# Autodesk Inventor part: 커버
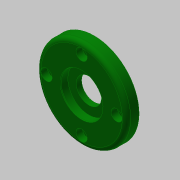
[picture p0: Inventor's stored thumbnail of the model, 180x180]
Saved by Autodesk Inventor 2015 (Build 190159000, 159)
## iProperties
Created: 2019-06
Part Number: 커버
Material: 알루미늄 6061
Document SubType Name: Modeling
Designer: mduedu
Density: 1 g/cm^3
Appearance: 진녹색
Author: mduedu
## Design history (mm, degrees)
sketch "스케치1"
  geometry: L1 (0, 0)-(9, 0); L2 (9, 0)-(9, 32); L3 (9, 32)-(0, 32); L4 (0, 32)-(0, 0); L5 (9, 0)-(12, 0); L6 (12, 0)-(12, 20); L7 (12, 20)-(9, 20); L8 (9, 20)-(9, 0)
  constraints: 16 end point, 4 parallel, 2 horizontal, 2 perpendicular
  dimensions: "d0" = 64 diameter of L3 L1; "d2" = 40 diameter of L7 L5; "d3" = 12 distance between parallel lines of L6 L4; "d4" = 3 distance between parallel lines of L2 L6
revolve "회전1" sketch "스케치1" stored, may be unused: angle "d5" = 90 deg
sketch "스케치2"
  geometry: L1 (0, 0)-(5.2, 0); L2 (5.2, 0)-(5.2, 15); L3 (5.2, 15)-(0, 15); L4 (0, 15)-(0, 0); L5 (5.2, 0)-(9, 0); L6 (9, 0)-(9, 9); L7 (9, 9)-(5.2, 9); L8 (5.2, 9)-(5.2, 0); L9 (9, 0)-(12, 0); L10 (12, 0)-(12, 15); L11 (12, 15)-(9, 15); L12 (9, 15)-(9, 0); L13 (12, -20)-(12, 20) reference
  constraints: 24 end point, 6 parallel, 3 horizontal, 3 perpendicular, 1 collinear
  dimensions: "d6" = 30 diameter of L3 L1; "d8" = 30 diameter of L11 L9; "d9" = 18 diameter of L7 L5; "d10" = 5.2 distance of L2.end L3.end; "d11" = 3 distance between parallel lines of L10 L12
revolve "회전2" sketch "스케치2" stored, may be unused: angle "d12" = 90 deg
fillet "모깎기1" dims "d13" = 3
fillet "모깎기2" dims "d14" = 3
chamfer "모따기1" distance "d15" = 1; stored, may be unused: second distance "d16" = 2, angle "d17" = 45 deg
sketch "스케치3" dims "d18" = 50
  geometry: 3 further points
  constraints: 2 vertical alignment, 1 coincident, 2 other
hole "구멍1" sketch "스케치3" at (0, 25) diameter "d19" = 4.5; stored, may be unused: countersink angle "d23" = 90 deg, drill point angle "d25" = 118 deg; dims "d20" = 6, "d21" = 8, "d22" = 4.6, "d24" = 8
chamfer "모따기2" distance "d29" = 0.5; stored, may be unused: second distance "d30" = 2, angle "d31" = 30 deg
node "솔리드1"
pattern_circular "원형 패턴1" dims angle "d27" = 360 deg
